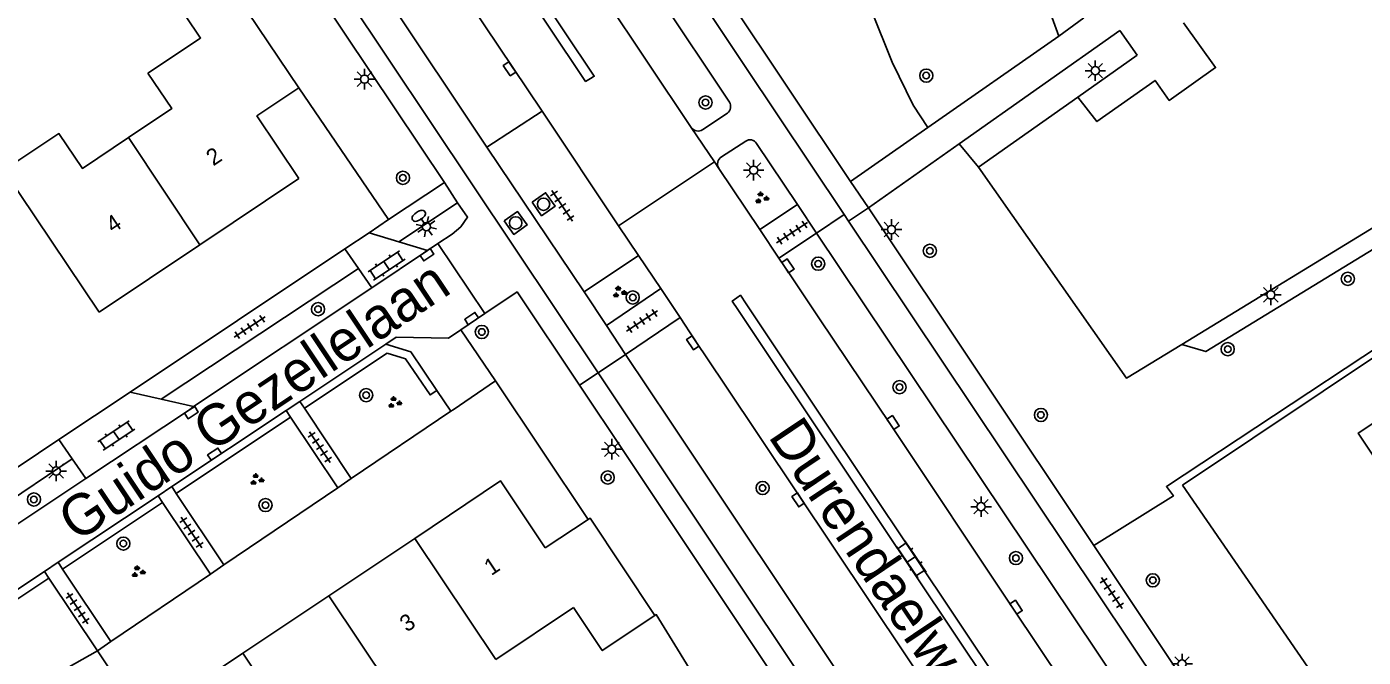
# Model space of a CAD drawing. Extents: x 137999 to 141000, y 397500 to 400501.
# Drawn here: x 138292.8 to 138374, y 399770.7 to 399809 of the extents above; entities that cross this region are included whole.
import ezdxf

# ---------------------------------------------------------------- set-up
doc = ezdxf.new("R2010")
doc.units = 0
for name, color, linetype in [('gg-afsc-erfafscheiding', 7, 'Continuous'), ('gg-afsc-hekwerk', 7, 'Continuous'), ('gg-anno-huisnummerreeks BGT', 7, 'Continuous'), ('gg-anno-openbare ruimte label', 7, 'Continuous'), ('gg-bbg-gedigitaliseerde bebouwing', 7, 'Continuous'), ('gg-bbg-hoofdgebouw', 7, 'Continuous'), ('gg-bbg-tussenscheiding', 7, 'Continuous'), ('gg-knt-verharding', 7, 'Continuous'), ('gg-knt-verharding nz', 7, 'Continuous'), ('gt-grn-groengrens', 7, 'Continuous'), ('gt-grn-vlakafsluiter', 7, 'Continuous'), ('gt-grn-weggrens', 7, 'Continuous'), ('gt-symb-boom', 7, 'Continuous'), ('gt-symb-brandkraan', 7, 'Continuous'), ('gt-symb-groenvak', 7, 'Continuous'), ('gt-symb-klinker verharding', 7, 'Continuous'), ('gt-symb-kolk', 7, 'Continuous'), ('gt-symb-lichtmast', 7, 'Continuous'), ('gt-symb-rioolschacht', 7, 'Continuous'), ('gt-symb-tegel verharding', 7, 'Continuous')]:
    doc.layers.add(name, color=color, linetype=linetype)

# ---------------------------------------------------------------- blocks, each defined once
blk = doc.blocks.new('gt0-LMAST')
at = {"layer": 'gt-symb-lichtmast'}
for p, q in [((-0.182, 0.173), (-0.447, 0.438)), ((-0.005, 0.246), (-0.005, 0.621)), ((0.172, 0.173), (0.437, 0.438)), ((-0.255, -0.004), (-0.63, -0.004)), ((-0.182, -0.181), (-0.447, -0.446)), ((-0.005, -0.254), (-0.005, -0.629)), ((0.437, -0.446), (0.172, -0.181)), ((0.245, -0.004), (0.62, -0.004))]:
    blk.add_line(p, q, dxfattribs=at)
blk.add_circle((-0.005, -0.004), 0.25, dxfattribs=at)
blk = doc.blocks.new('gt0-BOOM')
at = {"layer": 'gt-symb-boom'}
for radius in [0.4, 0.2]:
    blk.add_circle((0, 0), radius, dxfattribs=at)
blk = doc.blocks.new('gt0-KOLK')
at = {"layer": 'gt-symb-kolk'}
blk.add_lwpolyline([(0, 0), (0.375, 0), (0.375, 0.4), (-0.375, 0.4), (-0.375, 0), (0, 0)], dxfattribs=at)
blk = doc.blocks.new('gt0-BR')
at = {"layer": 'gt-symb-brandkraan'}
for centre, radius, start, end in [((-0.244, 0), 0.206, 107.56694, 252.43307), ((0.599, -2.664), 3, 106.89205, 107.56694), ((0, -0.691), 0.938, 73.10799, 106.89205), ((-0.599, -2.664), 3, 72.43309, 73.10799), ((0.244, 0), 0.206, 287.56695, 72.43309), ((0.599, 2.664), 3, 252.43307, 253.10797), ((0, 0.691), 0.938, 253.10797, 286.89206), ((-0.599, 2.664), 3, 286.89206, 287.56695)]:
    blk.add_arc(centre, radius, start, end, dxfattribs=at)
blk = doc.blocks.new('gt0-RS')
at = {"layer": 'gt-symb-rioolschacht'}
blk.add_lwpolyline([(-0.5, -0.5), (0.5, -0.5), (0.5, 0.5), (-0.5, 0.5)], close=True, dxfattribs=at)
blk.add_circle((0, 0), 0.375, dxfattribs=at)
blk = doc.blocks.new('gt0-TEG1')
at = {"layer": 'gt-symb-tegel verharding'}
for p, q in [((-1.125, 0), (1.125, 0)), ((-0.9, -0.25), (-0.9, 0.25)), ((-0.45, -0.25), (-0.45, 0.25)), ((0, -0.25), (0, 0.25)), ((0.45, -0.25), (0.45, 0.25)), ((0.9, -0.25), (0.9, 0.25))]:
    blk.add_line(p, q, dxfattribs=at)
blk = doc.blocks.new('gt0-GRVAK')
at = {"layer": 'gt-symb-groenvak'}
for p, q in [((-0.11, 0.189), (-0.228, 0.24)), ((-0.182, 0.153), (0.088, 0.153)), ((-0.091, 0.211), (-0.156, 0.322)), ((-0.047, 0.214), (-0.047, 0.393)), ((-0.004, 0.211), (0.061, 0.322)), ((0.015, 0.189), (0.133, 0.24)), ((0.262, -0.052), (0.197, 0.059)), ((0.305, -0.049), (0.305, 0.13)), ((0.349, -0.052), (0.414, 0.059)), ((-0.245, -0.228), (-0.363, -0.177)), ((-0.318, -0.264), (-0.047, -0.264)), ((-0.226, -0.206), (-0.291, -0.095)), ((-0.183, -0.203), (-0.183, -0.024)), ((-0.139, -0.206), (-0.074, -0.095)), ((-0.12, -0.228), (-0.002, -0.177)), ((0.243, -0.074), (0.125, -0.023)), ((0.17, -0.11), (0.441, -0.11)), ((0.368, -0.074), (0.486, -0.023))]:
    blk.add_line(p, q, dxfattribs=at)
blk = doc.blocks.new('gt0-KL1')
at = {"layer": 'gt-symb-klinker verharding'}
for p, q in [((-1.15, 0.3), (1.15, 0.3)), ((-1, -0.3), (-1, 0.3)), ((-0.5, 0.3), (-0.5, 0.45)), ((0, -0.3), (0, 0.3)), ((0.5, 0.3), (0.5, 0.45)), ((1, -0.3), (1, 0.3)), ((-1.15, -0.3), (1.15, -0.3)), ((-0.5, -0.45), (-0.5, -0.3)), ((0.5, -0.45), (0.5, -0.3))]:
    blk.add_line(p, q, dxfattribs=at)

msp = doc.modelspace()

# ---------------------------------------------------------------- linework, layer by layer
at = {"layer": 'gg-afsc-erfafscheiding'}
for p, q in [((138314.807, 399797.305), (138309.343, 399805.318)), ((138363.053, 399781.149), (138388.041, 399744.839))]:
    msp.add_line(p, q, dxfattribs=at)
msp.add_lwpolyline([(138334.05, 399768.45), (138331.076, 399773.286), (138330.993, 399773.231)], dxfattribs=at)
at = {"layer": 'gg-afsc-hekwerk'}
for p, q in [((138360.309, 399807.31), (138356.695, 399804.759)), ((138363.012, 399789.719), (138390.171, 399806.316)), ((138356.695, 399804.759), (138350.652, 399800.495)), ((138387.197, 399797.327), (138363.053, 399781.149))]:
    msp.add_line(p, q, dxfattribs=at)
msp.add_lwpolyline([(138350.652, 399800.495), (138359.65, 399787.664), (138363.012, 399789.719)], dxfattribs=at)
at = {"layer": 'gg-bbg-gedigitaliseerde bebouwing'}
for points in [[(138298.656, 399815.395), (138303.374, 399808.352), (138300.181, 399806.213)], [(138300.181, 399806.213), (138301.625, 399804.057), (138298.996, 399802.296)], [(138298.996, 399802.296), (138296.191, 399800.417), (138294.766, 399802.545), (138291.43, 399800.311), (138297.21, 399791.68)], [(138384.53, 399791.51), (138373.734, 399784.322), (138375.935, 399781.016), (138384.075, 399786.41), (138391.941, 399774.54), (138397.668, 399778.335), (138397.85, 399778.06)]]:
    msp.add_lwpolyline(points, dxfattribs=at)
at = {"layer": 'gg-bbg-hoofdgebouw'}
for p, q in [((138309.343, 399805.318), (138301.373, 399817.215)), ((138303.336, 399795.782), (138309.35, 399799.81)), ((138297.21, 399791.68), (138303.336, 399795.782)), ((138326.931, 399779.073), (138324.324, 399777.337)), ((138316.39, 399777.917), (138311.17, 399774.425)), ((138311.17, 399774.425), (138305.949, 399770.932)), ((138321.315, 399770.556), (138326.037, 399773.717))]:
    msp.add_line(p, q, dxfattribs=at)
for points in [[(138309.35, 399799.81), (138306.801, 399803.615), (138309.343, 399805.318)], [(138324.324, 399777.337), (138321.61, 399781.41), (138316.39, 399777.917)], [(138330.993, 399773.231), (138327.048, 399779.151), (138326.931, 399779.073)], [(138330.993, 399773.231), (138327.791, 399771.097), (138326.037, 399773.717)], [(138305.728, 399760.122), (138305.65, 399760.07), (138300.73, 399767.44), (138305.949, 399770.932)]]:
    msp.add_lwpolyline(points, dxfattribs=at)
at = {"layer": 'gg-bbg-tussenscheiding'}
for p, q in [((138298.996, 399802.296), (138303.336, 399795.782)), ((138316.39, 399777.917), (138321.315, 399770.556)), ((138311.17, 399774.425), (138316.095, 399767.062)), ((138305.949, 399770.932), (138310.876, 399763.568))]:
    msp.add_line(p, q, dxfattribs=at)
at = {"layer": 'gg-knt-verharding'}
for p, q in [((138309.996, 399842.732), (138335.521, 399804.459)), ((138307.692, 399841.112), (138333.203, 399802.905)), ((138327.535, 399787.99), (138293.661, 399838.756)), ((138298.633, 399834.905), (138320.78, 399801.717)), ((138342.884, 399799.636), (138320.659, 399832.936)), ((138298.178, 399829.514), (138318.2, 399799.57)), ((138349.625, 399825.052), (138355.53, 399808.47)), ((138355.53, 399808.47), (138347.57, 399802.91)), ((138349.48, 399801.918), (138359.248, 399808.802)), ((138359.248, 399808.802), (138360.309, 399807.31)), ((138324.13, 399803.898), (138320.78, 399801.717)), ((138328.783, 399796.934), (138324.13, 399803.898)), ((138333.899, 399802.784), (138335.4, 399803.785)), ((138347.57, 399802.91), (138342.884, 399799.636)), ((138335.036, 399801.12), (138336.517, 399802.079)), ((138337.155, 399801.943), (138339.646, 399798.223)), ((138326.691, 399792.91), (138320.78, 399801.717)), ((138343.961, 399798.029), (138349.48, 399801.918)), ((138334.875, 399800.425), (138337.375, 399796.706)), ((138318.2, 399799.57), (138314.807, 399797.305)), ((138318.998, 399798.326), (138315.436, 399795.96)), ((138337.375, 399796.706), (138339.646, 399798.223)), ((138339.646, 399798.223), (138340.806, 399796.491)), ((138343.961, 399798.029), (138357.661, 399777.48)), ((138313.616, 399796.511), (138314.807, 399797.305)), ((138342.765, 399797.216), (138342.494, 399797.621)), ((138370.228, 399756.121), (138342.765, 399797.216)), ((138312.141, 399795.526), (138313.616, 399796.511)), ((138315.436, 399795.96), (138313.616, 399796.511)), ((138329.995, 399795.12), (138328.783, 399796.934)), ((138337.375, 399796.706), (138338.527, 399794.97)), ((138338.527, 399794.97), (138340.806, 399796.491)), ((138340.806, 399796.491), (138368.581, 399755.018)), ((138299.094, 399786.818), (138312.141, 399795.526)), ((138312.141, 399795.526), (138312.966, 399794.336)), ((138313.778, 399793.165), (138317.178, 399795.433)), ((138317.178, 399795.433), (138315.436, 399795.96)), ((138317.178, 399795.433), (138317.798, 399795.846)), ((138317.798, 399795.846), (138320.654, 399791.591)), ((138329.995, 399795.12), (138326.691, 399792.91)), ((138331.355, 399793.11), (138329.995, 399795.12)), ((138338.527, 399794.97), (138339.164, 399794.002)), ((138300.992, 399786.385), (138312.966, 399794.336)), ((138312.966, 399794.336), (138313.778, 399793.165)), ((138339.164, 399794.002), (138341, 399791.263)), ((138302.947, 399785.939), (138313.778, 399793.165)), ((138331.355, 399793.11), (138328.038, 399790.863)), ((138332.521, 399791.363), (138331.355, 399793.11)), ((138326.691, 399792.91), (138328.038, 399790.863)), ((138336.537, 399792.186), (138338.36, 399789.456)), ((138319.2, 399790.611), (138320.654, 399791.591)), ((138337.856, 399789.111), (138336.035, 399791.836)), ((138319.2, 399790.611), (138321.31, 399787.498)), ((138329.206, 399789.105), (138328.038, 399790.863)), ((138332.521, 399791.363), (138329.206, 399789.105)), ((138333.403, 399790.012), (138332.521, 399791.363)), ((138309.408, 399786.251), (138314.645, 399789.74)), ((138335.215, 399787.302), (138333.403, 399790.012)), ((138331.916, 399785.044), (138329.206, 399789.105)), ((138362.984, 399751.516), (138337.856, 399789.111)), ((138338.36, 399789.456), (138363.498, 399751.825)), ((138321.31, 399787.498), (138326.931, 399779.073)), ((138330.259, 399783.908), (138327.535, 399787.99)), ((138294.757, 399783.923), (138299.094, 399786.818)), ((138300.992, 399786.385), (138299.094, 399786.818)), ((138318.595, 399785.657), (138317.737, 399786.922)), ((138329.132, 399783.136), (138326.399, 399787.232)), ((138302.947, 399785.939), (138300.992, 399786.385)), ((138301.626, 399781.068), (138308.575, 399785.697)), ((138308.575, 399785.697), (138309.408, 399786.251)), ((138308.575, 399785.697), (138308.852, 399785.281)), ((138309.408, 399786.251), (138309.685, 399785.835)), ((138309.685, 399785.835), (138312.539, 399781.551)), ((138308.852, 399785.281), (138311.71, 399780.989)), ((138356.902, 399747.607), (138331.916, 399785.044)), ((138282.044, 399775.438), (138294.757, 399783.923)), ((138294.757, 399783.923), (138295.575, 399782.749)), ((138355.234, 399746.49), (138330.259, 399783.908)), ((138283.697, 399774.807), (138295.575, 399782.749)), ((138295.575, 399782.749), (138296.396, 399781.569)), ((138341.079, 399765.233), (138329.132, 399783.136)), ((138285.327, 399774.184), (138296.396, 399781.569)), ((138300.793, 399780.514), (138301.626, 399781.068)), ((138301.626, 399781.068), (138301.903, 399780.652)), ((138294.718, 399776.466), (138300.793, 399780.514)), ((138300.793, 399780.514), (138301.07, 399780.098)), ((138301.07, 399780.098), (138303.972, 399775.741)), ((138301.903, 399780.652), (138304.8, 399776.303)), ((138357.661, 399777.48), (138371.385, 399756.895)), ((138293.886, 399775.912), (138294.718, 399776.466)), ((138294.718, 399776.466), (138294.995, 399776.05)), ((138294.995, 399776.05), (138297.929, 399771.644)), ((138285.547, 399770.358), (138293.886, 399775.912)), ((138293.886, 399775.912), (138294.163, 399775.496)), ((138294.163, 399775.496), (138297.103, 399771.084))]:
    msp.add_line(p, q, dxfattribs=at)
for points in [[(138342.494, 399797.621), (138336.437, 399806.685), (138308.333, 399848.857)], [(138301.724, 399844.305), (138327.3, 399806.031), (138327.072, 399805.893)], [(138327.072, 399805.893), (138326.772, 399805.71), (138301.233, 399843.961)], [(138324.13, 399803.898), (138315.385, 399816.968), (138307.904, 399828.206), (138301.948, 399837.117)], [(138356.695, 399804.759), (138357.856, 399803.273), (138361.388, 399805.777), (138362.25, 399804.559), (138365.068, 399806.553), (138363.107, 399809.282)], [(138317.798, 399795.846), (138318.671, 399796.429), (138319.203, 399796.878), (138319.602, 399797.448), (138318.998, 399798.326)], [(138326.399, 399787.232), (138322.611, 399792.909), (138320.654, 399791.591)], [(138336.035, 399791.836), (138335.692, 399792.349), (138335.969, 399792.552)], [(138335.969, 399792.552), (138336.186, 399792.711), (138336.537, 399792.186)], [(138314.645, 399789.74), (138315.26, 399790.15), (138318.44, 399790.1), (138319.2, 399790.611)], [(138341, 399791.263), (138345.298, 399784.849), (138352.777, 399773.616), (138366.25, 399753.48)], [(138317.737, 399786.922), (138316.15, 399789.262), (138314.645, 399789.74)], [(138360.241, 399749.866), (138355.419, 399757.098), (138348.463, 399767.468), (138335.215, 399787.302)]]:
    msp.add_lwpolyline(points, dxfattribs=at)
for centre, radius, start, end in [((138335.048, 399804.196), 0.541, 310.55658, 29.08817), ((138333.612, 399803.197), 0.503, 215.49393, 304.78141), ((138336.777, 399801.735), 0.431, 28.78872, 127.14446), ((138335.284, 399800.696), 0.491, 120.34768, 213.56677)]:
    msp.add_arc(centre, radius, start, end, dxfattribs=at)
at = {"layer": 'gg-knt-verharding nz'}
msp.add_lwpolyline([(138296.396, 399781.569), (138302.706, 399785.732), (138302.947, 399785.939)], dxfattribs=at)
at = {"layer": 'gt-grn-groengrens'}
for p, q in [((138349.48, 399801.918), (138350.652, 399800.495)), ((138309.685, 399785.835), (138314.722, 399789.191)), ((138318.595, 399785.657), (138318.723, 399785.744)), ((138301.903, 399780.652), (138308.852, 399785.281)), ((138312.539, 399781.551), (138318.595, 399785.657)), ((138304.8, 399776.303), (138311.71, 399780.989)), ((138311.71, 399780.989), (138312.539, 399781.551)), ((138294.995, 399776.05), (138301.07, 399780.098)), ((138303.972, 399775.741), (138304.8, 399776.303)), ((138286.038, 399770.084), (138294.163, 399775.496)), ((138297.929, 399771.644), (138303.972, 399775.741)), ((138297.103, 399771.084), (138297.929, 399771.644)), ((138305.121, 399759.042), (138297.103, 399771.084))]:
    msp.add_line(p, q, dxfattribs=at)
for points in [[(138347.57, 399802.91), (138346.686, 399804.262), (138345.413, 399806.887), (138344.141, 399810.069), (138343.186, 399813.33), (138343.266, 399815.796), (138344.141, 399819.535), (138345.057, 399821.948), (138349.625, 399825.052)], [(138357.661, 399777.48), (138362.497, 399780.505), (138362.072, 399781.065), (138381.588, 399793.964), (138392.328, 399801.118), (138390.62, 399805.284)], [(138363.012, 399789.719), (138364.471, 399789.285), (138390.62, 399805.284)], [(138317.737, 399786.922), (138317.323, 399786.642), (138315.833, 399788.838), (138314.722, 399789.191)], [(138295.381, 399768.552), (138294.777, 399769.761), (138297.103, 399771.084)]]:
    msp.add_lwpolyline(points, dxfattribs=at)
at = {"layer": 'gt-grn-vlakafsluiter'}
for p, q in [((138334.602, 399800.83), (138333.203, 399802.905)), ((138334.875, 399800.425), (138334.602, 399800.83)), ((138318.723, 399785.744), (138321.31, 399787.498))]:
    msp.add_line(p, q, dxfattribs=at)
at = {"layer": 'gt-grn-weggrens'}
for p, q in [((138357.06, 399809.58), (138355.53, 399808.47)), ((138334.602, 399800.83), (138328.783, 399796.934)), ((138318.2, 399799.57), (138318.998, 399798.326)), ((138343.961, 399798.029), (138342.884, 399799.636)), ((138343.961, 399798.029), (138342.765, 399797.216)), ((138342.494, 399797.621), (138340.806, 399796.491)), ((138329.206, 399789.105), (138327.535, 399787.99)), ((138327.535, 399787.99), (138326.399, 399787.232))]:
    msp.add_line(p, q, dxfattribs=at)

# ---------------------------------------------------------------- block references
at = {"layer": 'gt-symb-boom'}
for p in [(138347.482, 399806.067), (138334.069, 399804.434), (138315.677, 399799.85), (138347.702, 399795.407), (138340.915, 399794.626), (138373.098, 399793.708), (138310.515, 399791.856), (138329.641, 399792.574), (138320.47, 399790.473), (138365.802, 399789.425), (138345.857, 399787.117), (138313.443, 399786.633), (138328.122, 399781.616), (138337.536, 399780.982), (138293.25, 399780.286), (138307.32, 399779.944), (138298.683, 399777.6), (138352.933, 399776.719), (138361.249, 399775.366)]:
    msp.add_blockref('gt0-BOOM', p, dxfattribs=at)
at = {"layer": 'gt-symb-boom', "rotation": -55.92839019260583}
msp.add_blockref('gt0-BOOM', (138354.45, 399785.424), dxfattribs=at)
at = {"layer": 'gt-symb-brandkraan', "rotation": 33.705956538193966}
msp.add_blockref('gt0-BR', (138316.64, 399797.538), dxfattribs=at)
at = {"layer": 'gt-symb-groenvak'}
for p in [(138337.459, 399798.62), (138328.809, 399792.892), (138315.153, 399786.174), (138306.774, 399781.49), (138299.565, 399775.881)]:
    msp.add_blockref('gt0-GRVAK', p, dxfattribs=at)
at = {"layer": 'gt-symb-klinker verharding'}
for p, rotation in [((138314.681, 399794.515), 33.83302869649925), ((138298.254, 399784.175), 33.833028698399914), ((138346.575, 399776.646), 124.19864361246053)]:
    msp.add_blockref('gt0-KL1', p, dxfattribs=dict(at, rotation=rotation))
at = {"layer": 'gt-symb-kolk'}
for p, rotation in [((138322.318, 399806.592), 123.91251258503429), ((138317.249, 399795), 33.705956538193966), ((138338.905, 399794.389), -56.91369260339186), ((138319.962, 399791.125), 33.705956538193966), ((138333.458, 399789.927), 123.78542795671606), ((138302.706, 399785.732), -146.59418202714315), ((138345.298, 399784.849), -56.16697130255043), ((138304.338, 399782.873), 33.705956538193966), ((138339.855, 399780.369), 123.70595653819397), ((138352.777, 399773.616), -56.34172813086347)]:
    msp.add_blockref('gt0-KOLK', p, dxfattribs=dict(at, rotation=rotation))
at = {"layer": 'gt-symb-lichtmast'}
for p in [(138357.759, 399806.371), (138313.347, 399805.857), (138336.994, 399800.32), (138345.376, 399796.705), (138368.427, 399792.733), (138328.376, 399783.342), (138294.609, 399782.017), (138350.816, 399779.848), (138363.032, 399770.282)]:
    msp.add_blockref('gt0-LMAST', p, dxfattribs=at)
at = {"layer": 'gt-symb-lichtmast', "rotation": 33.578813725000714}
msp.add_blockref('gt0-LMAST', (138317.102, 399796.886), dxfattribs=at)
at = {"layer": 'gt-symb-rioolschacht', "rotation": -54.76864261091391}
for p in [(138324.221, 399798.242), (138322.526, 399797.104)]:
    msp.add_blockref('gt0-RS', p, dxfattribs=at)
at = {"layer": 'gt-symb-tegel verharding'}
for p, rotation in [((138325.361, 399798.152), -56.00796028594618), ((138339.329, 399796.516), 33.213540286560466), ((138306.364, 399790.771), -146.5005999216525), ((138330.212, 399791.139), 33.21354028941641), ((138310.63, 399783.469), -56.34172813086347), ((138302.826, 399778.271), -56.34172813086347), ((138358.76, 399774.597), -56.50059991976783), ((138295.908, 399773.663), -56.34172813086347)]:
    msp.add_blockref('gt0-TEG1', p, dxfattribs=dict(at, rotation=rotation))

# ---------------------------------------------------------------- texts
at = {"layer": 'gg-anno-huisnummerreeks BGT'}
for s, p in [('2', (138304.148, 399800.538)), ('4', (138298.051, 399796.455)), ('1', (138321.042, 399775.615)), ('3', (138315.91, 399772.181))]:
    msp.add_text(s, height=1, rotation=33.8, dxfattribs=at).set_placement(p)
at = {"layer": 'gg-anno-openbare ruimte label'}
for s, rotation, p in [('Guido Gezellelaan', 33.7, (138295.845, 399777.644)), ('Durendaelweg', 303.9, (138337.83, 399784.129))]:
    msp.add_text(s, height=2.5, rotation=rotation, dxfattribs=at).set_placement(p)

doc.saveas('drawing.dxf')
